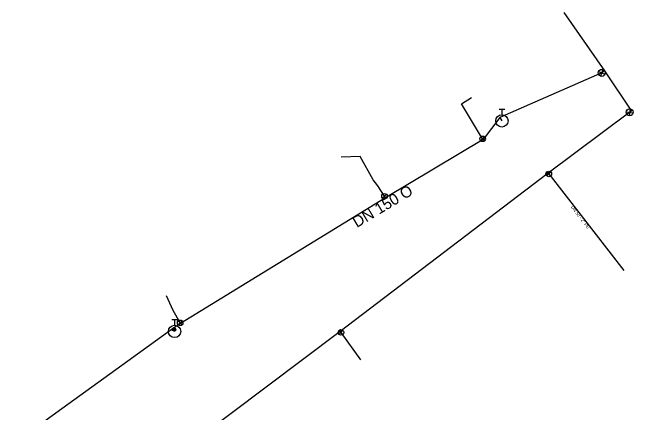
# Model space of a CAD drawing. Extents: x -451501 to -451094, y -1102108 to -1101623.
# Drawn here: x -451375.4 to -451286.4, y -1101680.8 to -1101623.4 of the extents above; entities that cross this region are included whole.
import ezdxf

# ---------------------------------------------------------------- set-up
doc = ezdxf.new("R2010")
doc.units = 0
for name, color, linetype in [('_hydrantova_odbocka_', 7, 'Continuous'), ('_pripojka_prevzato_z_dokumentace_', 7, 'Continuous'), ('_voda_smvak_prevzato_z_dokumentace_', 7, 'Continuous'), ('Default', 7, 'Continuous'), ('MoLevel 27', 7, 'Continuous'), ('MoLevel 28', 7, 'Continuous'), ('MoLevel 46', 7, 'Continuous'), ('MoLevel 53', 7, 'Continuous'), ('MoLevel 55', 7, 'Continuous')]:
    doc.layers.add(name, color=color, linetype=linetype)

# ---------------------------------------------------------------- blocks, each defined once
blk = doc.blocks.new('_uzaver_')
at = {"layer": 'Default'}
for p, q in [((-0.000035, -0.000035), (0.000035, 0.000035)), ((0.000035, -0.000035), (-0.000035, 0.000035))]:
    blk.add_line(p, q, dxfattribs=at)
for radius in [0.00005, 0.0000025]:
    blk.add_circle((0, 0), radius, dxfattribs=at)
blk = doc.blocks.new('_uzaver_pripojka_')
at = {"layer": 'Default'}
for p, q in [((-0.000035, -0.000035), (0.000035, 0.000035)), ((0.000035, -0.000035), (-0.000035, 0.000035))]:
    blk.add_line(p, q, dxfattribs=at)
for radius in [0.00005, 0.0000025]:
    blk.add_circle((0, 0), radius, dxfattribs=at)
blk = doc.blocks.new('_hydrant_voda_')
at = {"layer": 'Default'}
for p, q in [((-0.0000225, 0.000095), (0.0000225, 0.000095)), ((0, 0.000095), (0, 0.00005))]:
    blk.add_line(p, q, dxfattribs=at)
blk.add_circle((0, 0), 0.00005, dxfattribs=at)

msp = doc.modelspace()

# ---------------------------------------------------------------- linework, layer by layer
at = {"layer": '_hydrantova_odbocka_'}
msp.add_line((-451305.65, -1101638.53), (-451305.36, -1101639.01), dxfattribs=at)
msp.add_lwpolyline([(-451352.37, -1101668.69), (-451352.31, -1101668.89), (-451352.21, -1101669.17)], dxfattribs=at)
at = {"layer": '_pripojka_prevzato_z_dokumentace_'}
msp.add_line((-451352.4, -1101666.19), (-451353.36, -1101664.07), dxfattribs=at)
for points in [[(-451308.99, -1101640.14), (-451311.13, -1101636.54), (-451309.69, -1101635.65)], [(-451308.026, -1101641.66), (-451308.12, -1101641.57), (-451308.99, -1101640.14)], [(-451323.13, -1101648.3), (-451323.767, -1101647.444), (-451325.66, -1101644.12), (-451328.39, -1101644.2)], [(-451298.73, -1101646.49), (-451298.65, -1101646.6), (-451287.929, -1101660.465)], [(-451322.002, -1101650.019), (-451322.17, -1101649.8), (-451323.13, -1101648.3)], [(-451351.376, -1101668.037), (-451351.42, -1101667.95), (-451352.4, -1101666.19)], [(-451328.51, -1101669.18), (-451328.4, -1101669.32), (-451325.593, -1101673.26)]]:
    msp.add_lwpolyline(points, dxfattribs=at)
at = {"layer": '_voda_smvak_prevzato_z_dokumentace_'}
for p, q in [((-451296.507, -1101623.447), (-451290.65, -1101631.84)), ((-451290.65, -1101631.84), (-451291.07, -1101632.11)), ((-451290.65, -1101631.84), (-451286.82, -1101637.6)), ((-451286.82, -1101637.6), (-451287.07, -1101637.76))]:
    msp.add_line(p, q, dxfattribs=at)
for points in [[(-451291.07, -1101632.11), (-451305.65, -1101638.53), (-451308.026, -1101641.66), (-451322.002, -1101650.019), (-451351.376, -1101668.037), (-451352.37, -1101668.69)], [(-451287.07, -1101637.76), (-451298.73, -1101646.49), (-451328.51, -1101669.18), (-451365.13, -1101696.77), (-451388.63, -1101713.82), (-451391.04, -1101715.88)], [(-451352.37, -1101668.69), (-451374.89, -1101685.01), (-451391.639, -1101696.056), (-451420.33, -1101714.98), (-451434, -1101726.73), (-451445.03, -1101735.74), (-451449.89, -1101750.62)]]:
    msp.add_lwpolyline(points, dxfattribs=at)

# ---------------------------------------------------------------- block references
at = {"layer": 'MoLevel 27', "xscale": 10000}
for p, yscale, rotation in [((-451291.07, -1101632.11), 10000, -156.25172068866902), ((-451287.07, -1101637.76), 10000.000000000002, -143.177557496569)]:
    msp.add_blockref('_uzaver_', p, dxfattribs=dict(at, yscale=yscale, rotation=rotation))
at = {"layer": 'MoLevel 27', "xscale": 5000, "yscale": 5000}
msp.add_blockref('_uzaver_', (-451352.31, -1101668.89), dxfattribs=at)
at = {"layer": 'MoLevel 28', "xscale": 17636.68430335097, "yscale": 17636.68430335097}
for p in [(-451305.36, -1101639.01), (-451352.21, -1101669.17)]:
    msp.add_blockref('_hydrant_voda_', p, dxfattribs=at)
at = {"layer": 'MoLevel 53', "xscale": 7999.999999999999, "yscale": 7999.999999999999}
for p in [(-451308.12, -1101641.57), (-451298.65, -1101646.6), (-451322.17, -1101649.8), (-451351.42, -1101667.95), (-451328.4, -1101669.32)]:
    msp.add_blockref('_uzaver_pripojka_', p, dxfattribs=at)

# ---------------------------------------------------------------- texts
at = {"layer": 'MoLevel 46'}
msp.add_text('DN 150 O', height=1.6049, rotation=30.88351, dxfattribs=at).set_placement((-451326.129, -1101654.358))
at = {"layer": 'MoLevel 55'}
msp.add_text("DN 50 - 2'' PE", height=0.455, rotation=307.71352, dxfattribs=at).set_placement((-451295.522, -1101651.377))

doc.saveas('drawing.dxf')
